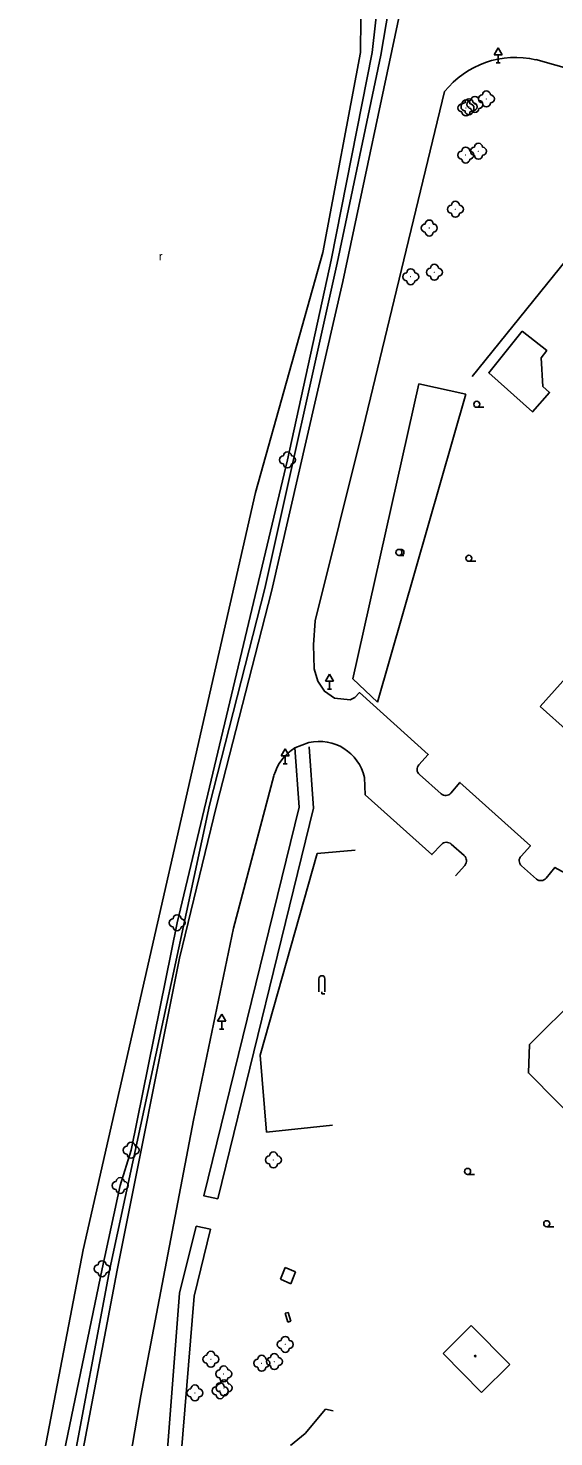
# Model space of a CAD drawing. Extents: x -737488 to -734267, y -1145775 to -1142573.
# Drawn here: x -736657.6 to -736592, y -1144304.9 to -1144128.9 of the extents above; entities that cross this region are included whole.
import ezdxf

# ---------------------------------------------------------------- set-up
doc = ezdxf.new("R2010")
doc.units = 0
for name, color, linetype in [('Vrstva 1', 7, 'Continuous'), ('Vrstva 10', 7, 'Continuous'), ('Vrstva 11', 7, 'Continuous'), ('Vrstva 12', 7, 'Continuous'), ('Vrstva 3', 7, 'Continuous'), ('Vrstva 4', 7, 'Continuous'), ('Vrstva 5', 7, 'Continuous'), ('Vrstva 8', 7, 'Continuous'), ('Vrstva 9', 7, 'Continuous')]:
    doc.layers.add(name, color=color, linetype=linetype)

# ---------------------------------------------------------------- blocks, each defined once
blk = doc.blocks.new('3.130')
at = {"layer": 'Vrstva 1'}
blk.add_circle((0, 0), 0.001, dxfattribs=at)
for centre, start, end in [((-1, 0), 90, 270), ((0, 1), 0, 180), ((1, 0), 270, 90), ((0, -1), 180, 360)]:
    blk.add_arc(centre, 1, start, end, dxfattribs=at)
blk = doc.blocks.new('3.019')
at = {"layer": 'Vrstva 1'}
blk.add_text('r', height=2, dxfattribs=at).set_placement((-0.496, -0.964))
blk = doc.blocks.new('3.040')
at = {"layer": 'Vrstva 1'}
blk.add_line((0, -0.75), (1.75, -0.75), dxfattribs=at)
blk.add_circle((0, 0), 0.75, dxfattribs=at)
blk = doc.blocks.new('3.100')
at = {"layer": 'Vrstva 1'}
for p, q in [((-0.75, 0), (-0.75, 3.25)), ((0.75, 0), (0.75, 3.25))]:
    blk.add_line(p, q, dxfattribs=at)
blk.add_lwpolyline([(0, 0), (0, -0.5), (0.75, -0.5)], dxfattribs=at)
blk.add_arc((0, 3.25), 0.75, 0, 180, dxfattribs=at)
blk = doc.blocks.new('3.110')
at = {"layer": 'Vrstva 1'}
blk.add_line((0, -0.75), (1.25, -0.75), dxfattribs=at)
blk.add_circle((0, 0), 0.75, dxfattribs=at)
blk.add_arc((0.5, 0), 0.75, 249.4944, 109.0474, dxfattribs=at)
blk = doc.blocks.new('4.020')
at = {"layer": 'Vrstva 1'}
blk.add_circle((0, 0), 0.175, dxfattribs=at)
blk = doc.blocks.new('5.270')
at = {"layer": 'Vrstva 1'}
for p, q in [((0, 3.732), (-1, 2)), ((0, 3.732), (1, 2)), ((-1, 2), (1, 2)), ((-0.5, 0), (0.5, 0)), ((0, 0), (0, 2))]:
    blk.add_line(p, q, dxfattribs=at)

msp = doc.modelspace()

# ---------------------------------------------------------------- linework, layer by layer
at = {"layer": 'Vrstva 10'}
for points in [[(-736618.35, -1144160.55), (-736610.79, -1144125.03)], [(-736594.21, -1144132.82), (-736589.24, -1144134.21)], [(-736615.8, -1144178.86), (-736605.64, -1144136.81)], [(-736627.26, -1144199.28), (-736618.35, -1144160.55)], [(-736608.84, -1144220.95), (-736607.66, -1144219.66), (-736616.27, -1144211.93), (-736616.85, -1144212.54), (-736617.41, -1144212.85), (-736619.37, -1144212.64), (-736620.62, -1144211.75), (-736621.44, -1144210.49), (-736621.93, -1144208.97), (-736622, -1144205.94), (-736621.79, -1144202.97), (-736615.8, -1144178.86)], [(-736634.13, -1144226.08), (-736627.26, -1144199.28)], [(-736622.57, -1144218.16), (-736624.32, -1144218.84)], [(-736624.32, -1144218.84), (-736623.8, -1144226.23), (-736635.7, -1144274.81), (-736633.94, -1144275.19)], [(-736622.52, -1144218.71), (-736621.99, -1144226.39), (-736633.94, -1144275.19)], [(-736632.01, -1144241.38), (-736626.94, -1144222.31)], [(-736606.01, -1144230.9), (-736607.2, -1144232.18), (-736615.53, -1144224.7), (-736615.63, -1144222.53)], [(-736608.77, -1144222.16), (-736606.06, -1144224.56)], [(-736604.85, -1144224.48), (-736603.71, -1144223.15), (-736594.9, -1144231.06), (-736596.07, -1144232.35)], [(-736638.72, -1144245.11), (-736634.13, -1144226.08)], [(-736604.81, -1144230.87), (-736603.19, -1144232.3)], [(-736603.09, -1144233.52), (-736604.25, -1144234.82)], [(-736596.02, -1144233.56), (-736594.15, -1144235.24)], [(-736592.95, -1144235.12), (-736591.84, -1144233.78), (-736586.24, -1144236.86)], [(-736637, -1144265.35), (-736632.01, -1144241.38)], [(-736646.51, -1144284.13), (-736638.72, -1144245.11)], [(-736643.56, -1144299.82), (-736637, -1144265.35)], [(-736634.88, -1144278.99), (-736636.65, -1144278.63), (-736638.72, -1144286.99), (-736642.04, -1144329.72), (-736648.67, -1144329.73)], [(-736640.4, -1144329.99), (-736636.92, -1144287.35), (-736634.88, -1144278.99)], [(-736651.57, -1144310.64), (-736646.51, -1144284.13)], [(-736648.67, -1144329.73), (-736643.56, -1144299.82)]]:
    msp.add_lwpolyline(points, dxfattribs=at)
for centre, radius, start, end in [((-736596.74, -1144143.94), 11.4, 77.1751, 141.3112), ((-736621.29, -1144223.82), 5.8, 12.8063, 102.7978), ((-736621.23, -1144223.89), 5.92, 121.411, 164.4802), ((-736608.21, -1144221.52), 0.847, 137.599, 229.0229), ((-736605.49, -1144223.95), 0.835, 227.1832, 320.382), ((-736605.4, -1144231.46), 0.833, 45.3652, 137.499), ((-736603.76, -1144232.96), 0.874, 320.2422, 49.1296), ((-736595.45, -1144232.93), 0.846, 136.6904, 228.0421), ((-736593.61, -1144234.58), 0.85, 230.5491, 320.8721)]:
    msp.add_arc(centre, radius, start, end, dxfattribs=at)
at = {"layer": 'Vrstva 11'}
for points in [[(-736616.13, -1144131.91), (-736616.04, -1144123.38)], [(-736620.85, -1144156.91), (-736616.13, -1144131.91)], [(-736629.25, -1144186.93), (-736620.85, -1144156.91)], [(-736617.08, -1144210.19), (-736608.84, -1144173.32)], [(-736602.98, -1144174.63), (-736608.84, -1144173.32)], [(-736613.99, -1144213.14), (-736602.98, -1144174.63)], [(-736650.78, -1144281.58), (-736629.25, -1144186.93)], [(-736613.99, -1144213.14), (-736617.08, -1144210.19)], [(-736627.86, -1144266.87), (-736628.64, -1144257.22), (-736621.56, -1144232.05)], [(-736621.56, -1144232.05), (-736616.78, -1144231.63)], [(-736619.64, -1144265.98), (-736627.86, -1144266.87)], [(-736657.64, -1144317.34), (-736650.78, -1144281.58)]]:
    msp.add_lwpolyline(points, dxfattribs=at)
at = {"layer": 'Vrstva 12'}
for points in [[(-736613.58, -1144132.26), (-736609.01, -1144105.3)], [(-736614.68, -1144131.93), (-736612.69, -1144114.09)], [(-736619.81, -1144157.89), (-736614.68, -1144131.93)], [(-736619.05, -1144158.24), (-736613.58, -1144132.26)], [(-736628.09, -1144198.92), (-736619.05, -1144158.24)], [(-736625.25, -1144182.84), (-736619.81, -1144157.89)], [(-736639.04, -1144240.7), (-736625.25, -1144182.84)], [(-736634.99, -1144226), (-736628.09, -1144198.92)], [(-736647.44, -1144283.94), (-736634.99, -1144226)], [(-736644.79, -1144269.12), (-736639.04, -1144240.7)], [(-736646.15, -1144273.53), (-736644.79, -1144269.12)], [(-736648.41, -1144283.94), (-736646.15, -1144273.53)], [(-736654.29, -1144312.24), (-736648.41, -1144283.94)], [(-736652.39, -1144310.37), (-736647.44, -1144283.94)]]:
    msp.add_lwpolyline(points, dxfattribs=at)
at = {"layer": 'Vrstva 4'}
for points in [[(-736593.7, -1144213.67), (-736582.24, -1144200.86), (-736570.79, -1144211.03), (-736572.78, -1144213.27), (-736571.41, -1144214.51), (-736578.3, -1144222.23), (-736580.34, -1144220.41), (-736581.31, -1144218.21), (-736586.93, -1144213.21), (-736590.14, -1144216.81), (-736593.7, -1144213.67)], [(-736588.01, -1144266.66), (-736595.16, -1144259.45), (-736595, -1144255.91), (-736588.96, -1144249.9), (-736585.15, -1144253.79), (-736582.71, -1144251.42), (-736577.69, -1144256.48), (-736588.01, -1144266.66)], [(-736625.54, -1144289.49), (-736625.18, -1144289.39)], [(-736625.21, -1144290.59), (-736625.54, -1144289.49)], [(-736625.21, -1144290.59), (-736624.85, -1144290.49)], [(-736625.18, -1144289.39), (-736624.85, -1144290.49)]]:
    msp.add_lwpolyline(points, dxfattribs=at)
at = {"layer": 'Vrstva 5'}
for points in [[(-736605.81, -1144294.52), (-736602.3, -1144291.04)], [(-736602.3, -1144291.04), (-736597.49, -1144295.9)], [(-736601, -1144299.38), (-736605.81, -1144294.52)], [(-736597.49, -1144295.9), (-736601, -1144299.38)]]:
    msp.add_lwpolyline(points, dxfattribs=at)
at = {"layer": 'Vrstva 9'}
for points in [[(-736578.58, -1144142.91), (-736582.75, -1144148.36), (-736602.16, -1144172.44)], [(-736595.95, -1144166.76), (-736600.11, -1144171.95), (-736594.66, -1144176.84), (-736592.5, -1144174.43), (-736593.34, -1144173.67), (-736593.56, -1144170.09), (-736592.87, -1144169.19), (-736595.95, -1144166.76)], [(-736626.13, -1144285.25), (-736625.52, -1144283.78)], [(-736624.84, -1144285.8), (-736626.13, -1144285.25)], [(-736625.52, -1144283.78), (-736624.23, -1144284.33)], [(-736624.84, -1144285.8), (-736624.23, -1144284.33)], [(-736620.51, -1144301.5), (-736623.02, -1144304.51)], [(-736620.51, -1144301.5), (-736619.54, -1144301.68)], [(-736624.86, -1144306.02), (-736623.02, -1144304.51)]]:
    msp.add_lwpolyline(points, dxfattribs=at)

# ---------------------------------------------------------------- block references
at = {"layer": 'Vrstva 11', "xscale": 0.5, "yscale": 0.5}
for p in [(-736601.84, -1144138.42), (-736600.4, -1144137.72), (-736602.95, -1144138.85), (-736602.57, -1144138.71), (-736602.98, -1144144.75), (-736601.39, -1144144.26), (-736604.27, -1144151.52), (-736607.54, -1144153.86), (-736606.9, -1144159.39), (-736609.85, -1144159.96), (-736625.25, -1144182.84), (-736639.04, -1144240.7), (-736644.79, -1144269.12), (-736627, -1144270.33), (-736646.15, -1144273.53), (-736648.41, -1144283.94), (-736625.52, -1144293.4), (-736634.82, -1144295.25), (-736628.46, -1144295.74), (-736626.88, -1144295.53), (-736633.2, -1144297.07), (-736636.82, -1144299.45), (-736633.66, -1144299.19), (-736633.16, -1144298.82)]:
    msp.add_blockref('3.130', p, dxfattribs=at)
at = {"layer": 'Vrstva 3', "xscale": 0.5, "yscale": 0.5}
for name, p in [('3.019', (-736641.05, -1144157.4)), ('3.040', (-736601.6, -1144175.89)), ('3.110', (-736611.32, -1144194.4)), ('3.040', (-736602.59, -1144195.14)), ('3.100', (-736620.95, -1144249.31)), ('3.040', (-736602.74, -1144271.77)), ('3.040', (-736592.87, -1144278.31))]:
    msp.add_blockref(name, p, dxfattribs=at)
at = {"layer": 'Vrstva 8', "xscale": 0.5, "yscale": 0.5}
msp.add_blockref('4.020', (-736601.8, -1144294.85), dxfattribs=at)
at = {"layer": 'Vrstva 9', "xscale": 0.5, "yscale": 0.5}
for p in [(-736598.93, -1144133.21), (-736619.98, -1144211.48), (-736625.52, -1144220.82), (-736633.47, -1144253.98)]:
    msp.add_blockref('5.270', p, dxfattribs=at)

doc.saveas('drawing.dxf')
